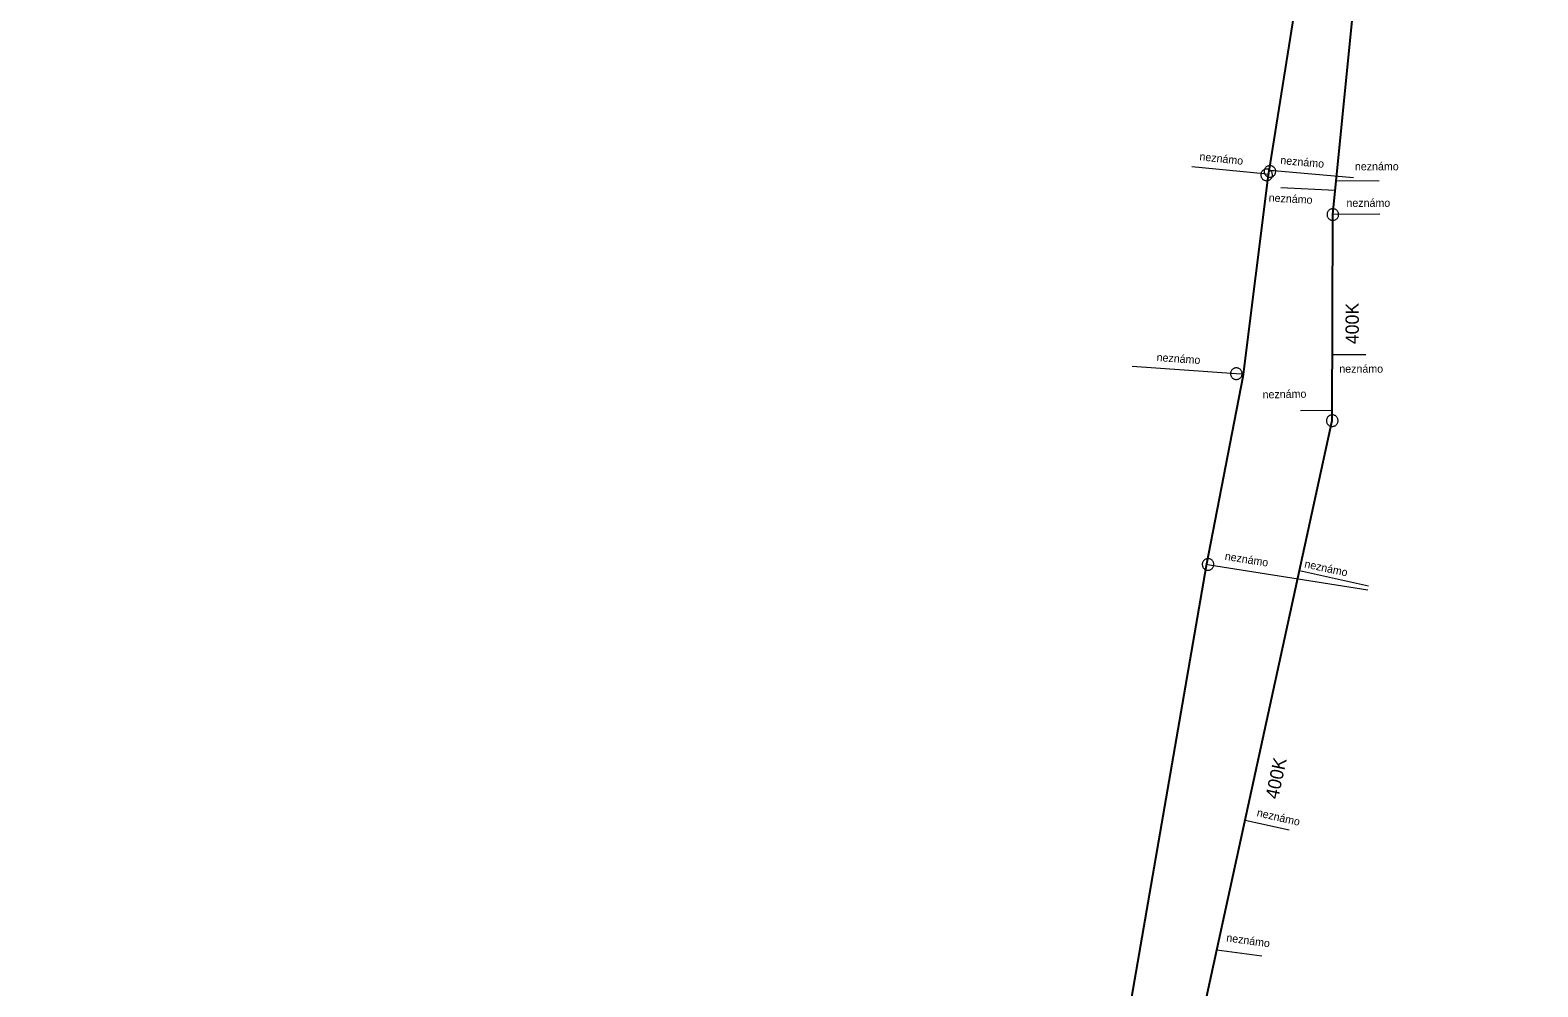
# Model space of a CAD drawing. Extents: x -741806 to -738704, y -1059275 to -1055387.
# Drawn here: x -740275.6 to -740162, y -1056620 to -1056547.9 of the extents above; entities that cross this region are included whole.
import ezdxf

# ---------------------------------------------------------------- set-up
doc = ezdxf.new("R2010")
doc.units = 0
doc.header["$LTSCALE"] = 0.4
for name, color, linetype, lineweight in [('2', 7, 'Continuous', 25), ('21', 7, 'Continuous', 13), ('3', 7, 'Continuous', 13), ('51', 7, 'Continuous', 13), ('52', 7, 'Continuous', 25), ('56', 7, 'Continuous', 13)]:
    doc.layers.add(name, color=color, linetype=linetype, lineweight=lineweight)
for name, color, linetype in [('5', 7, 'Continuous'), ('54', 7, 'Continuous'), ('55', 7, 'Continuous')]:
    doc.layers.add(name, color=color, linetype=linetype)

msp = doc.modelspace()

# ---------------------------------------------------------------- linework, layer by layer
at = {"layer": '2'}
msp.add_line((-740177.46, -1056577.32), (-740177.42, -1056561.79), dxfattribs=at)
for points in [[(-740177.42, -1056561.79), (-740175.219, -1056539.58), (-740169.98, -1056510.23), (-740124.77, -1056501.96)], [(-740211.579, -1056705.889), (-740203.5, -1056696.159), (-740199.899, -1056679.69), (-740189.57, -1056632.889), (-740177.46, -1056577.32)]]:
    msp.add_lwpolyline(points, dxfattribs=at)
at = {"layer": '21'}
for points in [[(-740182.28, -1056558.779), (-740182.612, -1056558.729), (-740188.039, -1056558.202)], [(-740182.228, -1056558.456), (-740181.866, -1056558.48), (-740175.868, -1056558.997)], [(-740184.181, -1056573.811), (-740184.699, -1056573.78), (-740192.535, -1056573.245)], [(-740186.93, -1056588.141), (-740186.706, -1056588.196), (-740174.775, -1056590.072)]]:
    msp.add_lwpolyline(points, dxfattribs=at)
at = {"layer": '3'}
for points in [[(-740177.417, -1056561.352), (-740177.462, -1056561.354), (-740177.507, -1056561.361), (-740177.552, -1056561.373), (-740177.594, -1056561.389), (-740177.635, -1056561.41), (-740177.674, -1056561.434), (-740177.71, -1056561.463), (-740177.743, -1056561.495), (-740177.771, -1056561.531), (-740177.796, -1056561.569), (-740177.817, -1056561.61), (-740177.834, -1056561.653), (-740177.846, -1056561.697), (-740177.854, -1056561.742), (-740177.856, -1056561.788), (-740177.854, -1056561.834), (-740177.846, -1056561.879), (-740177.836, -1056561.923), (-740177.819, -1056561.966), (-740177.798, -1056562.007), (-740177.773, -1056562.045), (-740177.745, -1056562.08), (-740177.712, -1056562.113), (-740177.678, -1056562.142), (-740177.639, -1056562.168), (-740177.598, -1056562.188), (-740177.556, -1056562.205), (-740177.511, -1056562.217), (-740177.466, -1056562.224), (-740177.42, -1056562.227), (-740177.375, -1056562.225), (-740177.33, -1056562.218), (-740177.285, -1056562.206), (-740177.242, -1056562.189), (-740177.202, -1056562.169), (-740177.163, -1056562.145), (-740177.127, -1056562.116), (-740177.094, -1056562.083), (-740177.066, -1056562.048), (-740177.041, -1056562.01), (-740177.02, -1056561.969), (-740177.003, -1056561.926), (-740176.99, -1056561.882), (-740176.983, -1056561.837), (-740176.981, -1056561.791), (-740176.983, -1056561.745), (-740176.99, -1056561.7), (-740177.001, -1056561.656), (-740177.018, -1056561.613), (-740177.039, -1056561.572), (-740177.064, -1056561.534), (-740177.092, -1056561.498), (-740177.125, -1056561.466), (-740177.159, -1056561.437), (-740177.198, -1056561.411), (-740177.239, -1056561.39), (-740177.281, -1056561.374), (-740177.326, -1056561.362), (-740177.371, -1056561.355), (-740177.416, -1056561.352)], [(-740177.367, -1056576.891), (-740177.412, -1056576.885), (-740177.457, -1056576.882), (-740177.504, -1056576.885), (-740177.548, -1056576.891), (-740177.593, -1056576.903), (-740177.636, -1056576.92), (-740177.676, -1056576.941), (-740177.715, -1056576.965), (-740177.75, -1056576.994), (-740177.783, -1056577.026), (-740177.812, -1056577.062), (-740177.837, -1056577.1), (-740177.857, -1056577.141), (-740177.875, -1056577.183), (-740177.886, -1056577.228), (-740177.894, -1056577.273), (-740177.896, -1056577.319), (-740177.894, -1056577.364), (-740177.887, -1056577.41), (-740177.875, -1056577.454), (-740177.858, -1056577.497), (-740177.838, -1056577.537), (-740177.813, -1056577.576), (-740177.785, -1056577.612), (-740177.752, -1056577.644), (-740177.716, -1056577.673), (-740177.678, -1056577.698), (-740177.637, -1056577.719), (-740177.594, -1056577.735), (-740177.55, -1056577.747), (-740177.505, -1056577.755), (-740177.46, -1056577.757), (-740177.413, -1056577.755), (-740177.368, -1056577.747), (-740177.325, -1056577.736), (-740177.281, -1056577.72), (-740177.241, -1056577.699), (-740177.202, -1056577.674), (-740177.167, -1056577.645), (-740177.134, -1056577.613), (-740177.105, -1056577.578), (-740177.08, -1056577.539), (-740177.059, -1056577.499), (-740177.042, -1056577.456), (-740177.031, -1056577.412), (-740177.023, -1056577.366), (-740177.02, -1056577.321), (-740177.023, -1056577.275), (-740177.031, -1056577.23), (-740177.042, -1056577.185), (-740177.059, -1056577.143), (-740177.079, -1056577.102), (-740177.104, -1056577.063), (-740177.132, -1056577.028), (-740177.165, -1056576.995), (-740177.201, -1056576.966), (-740177.239, -1056576.941), (-740177.28, -1056576.92), (-740177.323, -1056576.904), (-740177.366, -1056576.892)]]:
    msp.add_lwpolyline(points, dxfattribs=at)
at = {"layer": '51'}
for points in [[(-740182.841, -1056558.733), (-740182.846, -1056558.778), (-740182.846, -1056558.824), (-740182.841, -1056558.87), (-740182.831, -1056558.914), (-740182.817, -1056558.958), (-740182.798, -1056559), (-740182.775, -1056559.039), (-740182.748, -1056559.076), (-740182.717, -1056559.109), (-740182.683, -1056559.14), (-740182.645, -1056559.167), (-740182.605, -1056559.19), (-740182.564, -1056559.208), (-740182.52, -1056559.222), (-740182.475, -1056559.231), (-740182.429, -1056559.236), (-740182.384, -1056559.236), (-740182.338, -1056559.231), (-740182.293, -1056559.22), (-740182.25, -1056559.206), (-740182.208, -1056559.187), (-740182.169, -1056559.164), (-740182.132, -1056559.137), (-740182.098, -1056559.106), (-740182.067, -1056559.071), (-740182.041, -1056559.034), (-740182.018, -1056558.995), (-740182, -1056558.952), (-740181.986, -1056558.909), (-740181.976, -1056558.864), (-740181.972, -1056558.819), (-740181.973, -1056558.773), (-740181.978, -1056558.727), (-740181.987, -1056558.683), (-740182.002, -1056558.639), (-740182.021, -1056558.597), (-740182.044, -1056558.558), (-740182.071, -1056558.521), (-740182.102, -1056558.488), (-740182.136, -1056558.457), (-740182.173, -1056558.43), (-740182.213, -1056558.407), (-740182.255, -1056558.39), (-740182.298, -1056558.375), (-740182.344, -1056558.366), (-740182.389, -1056558.361), (-740182.435, -1056558.362), (-740182.48, -1056558.366), (-740182.525, -1056558.377), (-740182.569, -1056558.391), (-740182.61, -1056558.41), (-740182.65, -1056558.433), (-740182.687, -1056558.46), (-740182.721, -1056558.491), (-740182.751, -1056558.526), (-740182.778, -1056558.563), (-740182.8, -1056558.602), (-740182.819, -1056558.645), (-740182.833, -1056558.688), (-740182.841, -1056558.732)], [(-740181.724, -1056558.57), (-740181.722, -1056558.525), (-740181.726, -1056558.48), (-740181.735, -1056558.434), (-740181.748, -1056558.391), (-740181.766, -1056558.349), (-740181.789, -1056558.308), (-740181.815, -1056558.271), (-740181.845, -1056558.236), (-740181.879, -1056558.205), (-740181.915, -1056558.178), (-740181.955, -1056558.154), (-740181.996, -1056558.134), (-740182.039, -1056558.119), (-740182.084, -1056558.109), (-740182.13, -1056558.104), (-740182.176, -1056558.103), (-740182.221, -1056558.107), (-740182.266, -1056558.116), (-740182.31, -1056558.13), (-740182.352, -1056558.148), (-740182.392, -1056558.17), (-740182.43, -1056558.196), (-740182.464, -1056558.226), (-740182.495, -1056558.259), (-740182.523, -1056558.297), (-740182.546, -1056558.336), (-740182.565, -1056558.377), (-740182.58, -1056558.421), (-740182.59, -1056558.465), (-740182.597, -1056558.511), (-740182.597, -1056558.556), (-740182.593, -1056558.601), (-740182.584, -1056558.647), (-740182.571, -1056558.69), (-740182.553, -1056558.732), (-740182.53, -1056558.773), (-740182.504, -1056558.81), (-740182.474, -1056558.845), (-740182.44, -1056558.876), (-740182.404, -1056558.903), (-740182.365, -1056558.927), (-740182.323, -1056558.947), (-740182.28, -1056558.961), (-740182.235, -1056558.972), (-740182.19, -1056558.977), (-740182.144, -1056558.978), (-740182.098, -1056558.973), (-740182.053, -1056558.965), (-740182.009, -1056558.951), (-740181.967, -1056558.933), (-740181.927, -1056558.911), (-740181.89, -1056558.885), (-740181.855, -1056558.855), (-740181.824, -1056558.822), (-740181.796, -1056558.784), (-740181.773, -1056558.745), (-740181.754, -1056558.704), (-740181.739, -1056558.66), (-740181.729, -1056558.616), (-740181.724, -1056558.571)], [(-740185.128, -1056573.754), (-740185.128, -1056573.799), (-740185.124, -1056573.844), (-740185.115, -1056573.89), (-740185.101, -1056573.932), (-740185.083, -1056573.975), (-740185.06, -1056574.015), (-740185.034, -1056574.052), (-740185.004, -1056574.087), (-740184.969, -1056574.117), (-740184.933, -1056574.144), (-740184.893, -1056574.167), (-740184.851, -1056574.187), (-740184.808, -1056574.202), (-740184.764, -1056574.211), (-740184.718, -1056574.216), (-740184.672, -1056574.217), (-740184.627, -1056574.213), (-740184.582, -1056574.203), (-740184.538, -1056574.189), (-740184.496, -1056574.171), (-740184.456, -1056574.148), (-740184.419, -1056574.122), (-740184.385, -1056574.091), (-740184.354, -1056574.058), (-740184.326, -1056574.021), (-740184.303, -1056573.981), (-740184.284, -1056573.94), (-740184.27, -1056573.896), (-740184.26, -1056573.851), (-740184.254, -1056573.806), (-740184.254, -1056573.76), (-740184.259, -1056573.715), (-740184.268, -1056573.669), (-740184.281, -1056573.627), (-740184.3, -1056573.584), (-740184.323, -1056573.544), (-740184.349, -1056573.507), (-740184.379, -1056573.472), (-740184.414, -1056573.442), (-740184.45, -1056573.415), (-740184.49, -1056573.392), (-740184.531, -1056573.372), (-740184.575, -1056573.358), (-740184.619, -1056573.348), (-740184.665, -1056573.343), (-740184.711, -1056573.342), (-740184.756, -1056573.347), (-740184.801, -1056573.356), (-740184.845, -1056573.37), (-740184.887, -1056573.388), (-740184.927, -1056573.411), (-740184.964, -1056573.437), (-740184.998, -1056573.468), (-740185.029, -1056573.501), (-740185.057, -1056573.538), (-740185.08, -1056573.578), (-740185.098, -1056573.619), (-740185.113, -1056573.663), (-740185.123, -1056573.708), (-740185.128, -1056573.753)]]:
    msp.add_lwpolyline(points, dxfattribs=at)
msp.add_lwpolyline([(-740186.398, -1056588.262), (-740186.389, -1056588.217), (-740186.385, -1056588.172), (-740186.385, -1056588.125), (-740186.391, -1056588.081), (-740186.401, -1056588.036), (-740186.416, -1056587.992), (-740186.436, -1056587.951), (-740186.459, -1056587.911), (-740186.487, -1056587.876), (-740186.518, -1056587.842), (-740186.553, -1056587.812), (-740186.59, -1056587.785), (-740186.63, -1056587.763), (-740186.672, -1056587.745), (-740186.716, -1056587.732), (-740186.761, -1056587.723), (-740186.807, -1056587.719), (-740186.852, -1056587.72), (-740186.898, -1056587.726), (-740186.943, -1056587.736), (-740186.986, -1056587.751), (-740187.027, -1056587.77), (-740187.066, -1056587.794), (-740187.103, -1056587.821), (-740187.137, -1056587.853), (-740187.167, -1056587.888), (-740187.193, -1056587.925), (-740187.215, -1056587.965), (-740187.233, -1056588.007), (-740187.247, -1056588.051), (-740187.255, -1056588.096), (-740187.259, -1056588.141), (-740187.258, -1056588.187), (-740187.253, -1056588.232), (-740187.242, -1056588.277), (-740187.227, -1056588.321), (-740187.208, -1056588.362), (-740187.185, -1056588.402), (-740187.157, -1056588.437), (-740187.126, -1056588.471), (-740187.091, -1056588.501), (-740187.053, -1056588.528), (-740187.013, -1056588.549), (-740186.972, -1056588.568), (-740186.927, -1056588.581), (-740186.882, -1056588.59), (-740186.837, -1056588.593), (-740186.791, -1056588.593), (-740186.745, -1056588.587), (-740186.701, -1056588.577), (-740186.658, -1056588.562), (-740186.616, -1056588.543), (-740186.577, -1056588.519), (-740186.54, -1056588.492), (-740186.507, -1056588.46), (-740186.476, -1056588.425), (-740186.451, -1056588.388), (-740186.428, -1056588.348), (-740186.411, -1056588.306)], close=True, dxfattribs=at)
at = {"layer": '52'}
msp.add_lwpolyline([(-740175.489, -1056516.148), (-740182.237, -1056558.509), (-740182.283, -1056558.799), (-740184.208, -1056574.021), (-740186.954, -1056588.264), (-740195.633, -1056638.315), (-740197.478, -1056649.388), (-740200.254, -1056663.476), (-740207.839, -1056691.395), (-740209.772, -1056694), (-740210.063, -1056694.828), (-740213.269, -1056698.987), (-740231.234, -1056717.463), (-740244.285, -1056733.611), (-740248.473, -1056741.574), (-740255.759, -1056760.318), (-740256.949, -1056764.72), (-740259.395, -1056771.79), (-740264.607, -1056786.706), (-740265.408, -1056790.486), (-740270.787, -1056807.514), (-740272.432, -1056813.382), (-740275.537, -1056822.95), (-740275.601, -1056823.152)], dxfattribs=at)
at = {"layer": '56'}
for p, q in [((-740181.335, -1056559.754), (-740177.238, -1056559.949)), ((-740173.914, -1056559.26), (-740177.168, -1056559.242)), ((-740173.87, -1056561.764), (-740177.42, -1056561.79)), ((-740174.92, -1056572.362), (-740177.447, -1056572.37)), ((-740179.844, -1056576.549), (-740177.458, -1056576.52)), ((-740174.721, -1056589.783), (-740179.925, -1056588.634)), ((-740180.714, -1056608.19), (-740184.026, -1056607.453)), ((-740182.758, -1056617.688), (-740186.158, -1056617.233))]:
    msp.add_line(p, q, dxfattribs=at)

# ---------------------------------------------------------------- texts
at = {"layer": '5'}
for rotation, p in [(90, (-740175.459, -1056571.559)), (78, (-740181.537, -1056605.893))]:
    msp.add_text('400K', height=1, rotation=rotation, dxfattribs=at).set_placement(p)
at = {"layer": '54'}
for rotation, p in [(354, (-740187.491, -1056557.695)), (355, (-740181.392, -1056557.977)), (356, (-740190.715, -1056572.825)), (351, (-740185.592, -1056587.805))]:
    msp.add_text('neznámo ', height=0.6, rotation=rotation, dxfattribs=at).set_placement(p)
at = {"layer": '55'}
for p in [(-740175.755, -1056558.453), (-740176.392, -1056561.208), (-740176.93, -1056573.705)]:
    msp.add_text('neznámo ', height=0.6, dxfattribs=at).set_placement(p)
for rotation, p in [(357, (-740182.263, -1056560.807)), (1, (-740182.708, -1056575.647)), (348, (-740179.598, -1056588.377)), (347, (-740183.187, -1056607.118)), (352, (-740185.47, -1056616.559))]:
    msp.add_text('neznámo ', height=0.6, rotation=rotation, dxfattribs=at).set_placement(p)

doc.saveas('drawing.dxf')
